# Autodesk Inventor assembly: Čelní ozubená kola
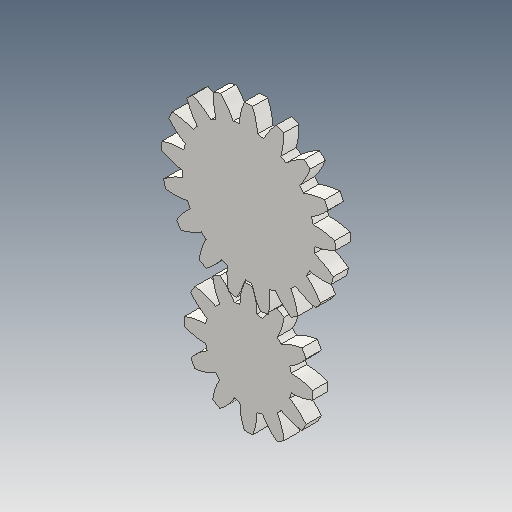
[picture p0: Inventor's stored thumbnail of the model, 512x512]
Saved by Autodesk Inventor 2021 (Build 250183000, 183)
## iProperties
ClientObjectVersion: 1
Created: 2024-11
Part Number: Čelní ozubená kola
Document SubType Name: Assembly
Designer: tatulinek
Categories: <?xml version="1.0" encoding="UTF-16"?> <MemberInstance><Categories><FamilyTemplate/><ParamToTemplateMap><ParamToTemplate><ParamToTemplate CategoryParameter="//
Author: tatulinek
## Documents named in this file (3)
- C:\Users\tatulinek\Documents\____Zviratka\Ozubena kola smazat3\Design Accelerator\Čelní ozubená kola1.iam
- C:\Users\tatulinek\Documents\____Zviratka\Ozubena kola smazat3\Design Accelerator\Čelní ozubené kolo11.ipt
- C:\Users\tatulinek\Documents\____Zviratka\Ozubena kola smazat3\Design Accelerator\Čelní ozubené kolo21.ipt
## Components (2 placed, 2 different names)
1. Čelní ozubené kolo1:1 — Rotace:1
2. Čelní ozubené kolo2:1 — Rotace:1
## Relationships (1: RelateRotation 1)
- Rotace:1 [RelateRotation]: Čelní ozubené kolo1:1 ↔ Čelní ozubené kolo2:1
